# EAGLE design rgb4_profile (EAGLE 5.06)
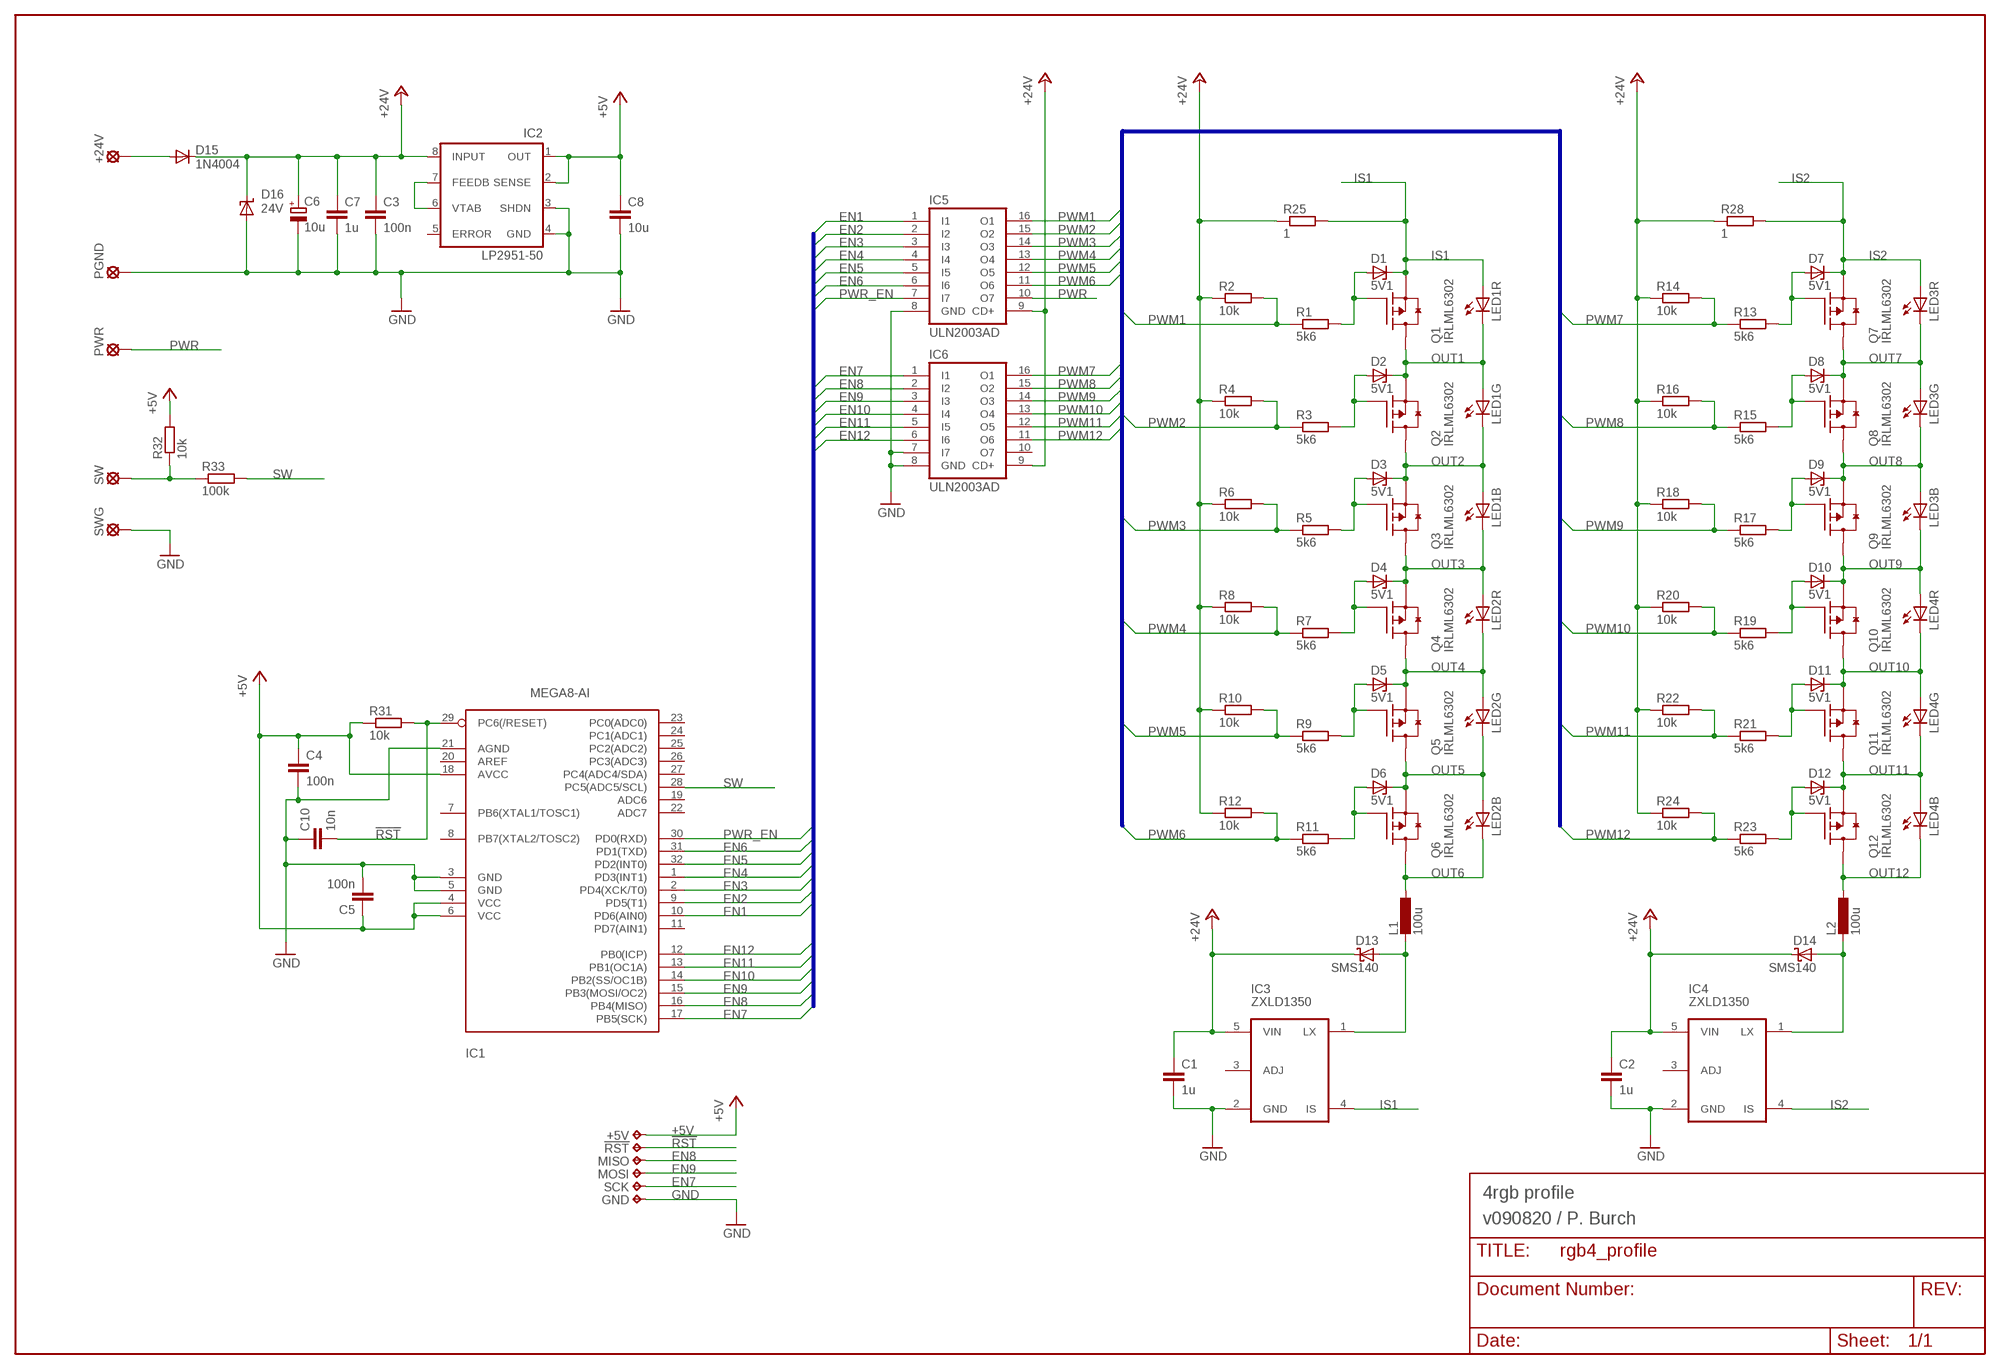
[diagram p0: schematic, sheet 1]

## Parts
!RST  TPB1,27  [B1,27]
+5V  TPB1,27  [B1,27]
+24V  SMD_4X2  [SMD4X2]
C1  1u  C-EUC1206  [C1206]
C2  1u  C-EUC1206  [C1206]
C3  100n  C-EUC0603  [C0603]
C4  100n  C-EUC0603  [C0603]
C5  100n  C-EUC0603  [C0603]
C6  10u  CPOL-EUD  [PANASONIC_D]
C7  1u  C-EUC1206  [C1206]
C8  10u  C-EUC1206  [C1206]
C10  10n  C-EUC0603  [C0603]
D1  5V1  ZENER-DIODESOD80C  [SOD80C]
D2  5V1  ZENER-DIODESOD80C  [SOD80C]
D3  5V1  ZENER-DIODESOD80C  [SOD80C]
D4  5V1  ZENER-DIODESOD80C  [SOD80C]
D5  5V1  ZENER-DIODESOD80C  [SOD80C]
D6  5V1  ZENER-DIODESOD80C  [SOD80C]
D7  5V1  ZENER-DIODESOD80C  [SOD80C]
D8  5V1  ZENER-DIODESOD80C  [SOD80C]
D9  5V1  ZENER-DIODESOD80C  [SOD80C]
D10  5V1  ZENER-DIODESOD80C  [SOD80C]
D11  5V1  ZENER-DIODESOD80C  [SOD80C]
D12  5V1  ZENER-DIODESOD80C  [SOD80C]
D13  SMS140  SCHOTTKY-DIODESMD  [SMB]
D14  SMS140  SCHOTTKY-DIODESMD  [SMB]
D15  1N4004  DIODE-MELF-MLL41  [MELF-MLL41]
D16  24V  SUPPRESSOR-SMBJ  [SMBJ]
GND  TPB1,27  [B1,27]
IC1  MEGA8-AI  [TQFP32-08]
IC2  LP2951-50  LP2951ACM  [SO-08]
IC3  ZXLD1350  [SOT23-5]
IC4  ZXLD1350  [SOT23-5]
IC5  ULN2003AD  [SO16]
IC6  ULN2003AD  [SO16]
L1  100u  L-EUX  [X]
L2  100u  L-EUX  [X]
LED1  SEOUL_ZPOWER_RGB  [SEOUL_P5]
LED2  SEOUL_ZPOWER_RGB  [SEOUL_P5]
LED3  SEOUL_ZPOWER_RGB  [SEOUL_P5]
LED4  SEOUL_ZPOWER_RGB  [SEOUL_P5]
MISO  TPB1,27  [B1,27]
MOSI  TPB1,27  [B1,27]
PGND  SMD_4X2  [SMD4X2]
PWR  SMD_4X2  [SMD4X2]
Q1  IRLML6302  [SOT23]
Q2  IRLML6302  [SOT23]
Q3  IRLML6302  [SOT23]
Q4  IRLML6302  [SOT23]
Q5  IRLML6302  [SOT23]
Q6  IRLML6302  [SOT23]
Q7  IRLML6302  [SOT23]
Q8  IRLML6302  [SOT23]
Q9  IRLML6302  [SOT23]
Q10  IRLML6302  [SOT23]
Q11  IRLML6302  [SOT23]
Q12  IRLML6302  [SOT23]
R1  5k6  R-EU_R0603  [R0603]
R2  10k  R-EU_R0603  [R0603]
R3  5k6  R-EU_R0603  [R0603]
R4  10k  R-EU_R0603  [R0603]
R5  5k6  R-EU_R0603  [R0603]
R6  10k  R-EU_R0603  [R0603]
R7  5k6  R-EU_R0603  [R0603]
R8  10k  R-EU_R0603  [R0603]
R9  5k6  R-EU_R0603  [R0603]
R10  10k  R-EU_R0603  [R0603]
R11  5k6  R-EU_R0603  [R0603]
R12  10k  R-EU_R0603  [R0603]
R13  5k6  R-EU_R0603  [R0603]
R14  10k  R-EU_R0603  [R0603]
R15  5k6  R-EU_R0603  [R0603]
R16  10k  R-EU_R0603  [R0603]
R17  5k6  R-EU_R0603  [R0603]
R18  10k  R-EU_R0603  [R0603]
R19  5k6  R-EU_R0603  [R0603]
R20  10k  R-EU_R0603  [R0603]
R21  5k6  R-EU_R0603  [R0603]
R22  10k  R-EU_R0603  [R0603]
R23  5k6  R-EU_R0603  [R0603]
R24  10k  R-EU_R0603  [R0603]
R25  1  R-EU_R0603  [R0603]
R28  1  R-EU_R0603  [R0603]
R31  10k  R-EU_R0603  [R0603]
R32  10k  R-EU_R0603  [R0603]
R33  100k  R-EU_R0603  [R0603]
SCK  TPB1,27  [B1,27]
SW  SMD_4X2  [SMD4X2]
SWG  SMD_4X2  [SMD4X2]

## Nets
!RST: !RST.PP(TP) C10.2 IC1.29(PC6(/RESET)) R31.2
+5V: +5V.PP(TP) C4.1 C5.1 C8.1 IC1.4(VCC) IC1.6(VCC) IC1.18(AVCC) IC2.1(OUT) IC2.2(SENSE) R31.1 R32.2
+24V: C1.1 C2.1 C3.1 C6.+ C7.1 D13.C D14.C D15.C D16.C IC2.8(INPUT) IC3.5(VIN) IC4.5(VIN) IC5.9(CD+) IC6.9(CD+) R2.1 R4.1 R6.1 R8.1 R10.1 R12.1 R14.1 R16.1 R18.1 R20.1 R22.1 R24.1 R25.1 R28.1
EN1: IC1.10(PD6(AIN0)) IC5.1(I1)
EN2: IC1.9(PD5(T1)) IC5.2(I2)
EN3: IC1.2(PD4(XCK/T0)) IC5.3(I3)
EN4: IC1.1(PD3(INT1)) IC5.4(I4)
EN5: IC1.32(PD2(INT0)) IC5.5(I5)
EN6: IC1.31(PD1(TXD)) IC5.6(I6)
EN7: IC1.17(PB5(SCK)) IC6.1(I1) SCK.PP(TP)
EN8: IC1.16(PB4(MISO)) IC6.2(I2) MISO.PP(TP)
EN9: IC1.15(PB3(MOSI/OC2)) IC6.3(I3) MOSI.PP(TP)
EN10: IC1.14(PB2(SS/OC1B)) IC6.4(I4)
EN11: IC1.13(PB1(OC1A)) IC6.5(I5)
EN12: IC1.12(PB0(ICP)) IC6.6(I6)
GND: C1.2 C2.2 C3.2 C4.2 C5.2 C6.- C7.2 C8.2 C10.1 D16.A GND.PP(TP) IC1.3(GND) IC1.5(GND) IC1.21(AGND) IC2.3(SHDN) IC2.4(GND) IC3.2(GND) IC4.2(GND) IC5.8(GND) IC6.7(I7) IC6.8(GND) PGND.PAD(MP) SWG.PAD(MP)
IS1: D1.C IC3.4(IS) LED1.RA(R:A) Q1.2(S) R25.2
IS2: D7.C IC4.4(IS) LED3.RA(R:A) Q7.2(S) R28.2
N$1: IC2.6(VTAB) IC2.7(FEEDB)
N$2: R32.1 R33.1 SW.PAD(MP)
N$3: D13.A IC3.1(LX) L1.P$2
N$4: D14.A IC4.1(LX) L2.P$2
N$5: D1.A Q1.1(G) R1.2
N$7: +24V.PAD(MP) D15.A
N$16: D2.A Q2.1(G) R3.2
N$17: D3.A Q3.1(G) R5.2
N$18: D4.A Q4.1(G) R7.2
N$19: D5.A Q5.1(G) R9.2
N$20: D6.A Q6.1(G) R11.2
N$21: D7.A Q7.1(G) R13.2
N$22: D8.A Q8.1(G) R15.2
N$23: D9.A Q9.1(G) R17.2
N$24: D10.A Q10.1(G) R19.2
N$25: D11.A Q11.1(G) R21.2
N$26: D12.A Q12.1(G) R23.2
OUT1: D2.C LED1.GA(G:A) LED1.RK(R:C) Q1.3(D) Q2.2(S)
OUT2: D3.C LED1.BA(B:A) LED1.GK(G:C) Q2.3(D) Q3.2(S)
OUT3: D4.C LED1.BK(B:C) LED2.RA(R:A) Q3.3(D) Q4.2(S)
OUT4: D5.C LED2.GA(G:A) LED2.RK(R:C) Q4.3(D) Q5.2(S)
OUT5: D6.C LED2.BA(B:A) LED2.GK(G:C) Q5.3(D) Q6.2(S)
OUT6: L1.P$1 LED2.BK(B:C) Q6.3(D)
OUT7: D8.C LED3.GA(G:A) LED3.RK(R:C) Q7.3(D) Q8.2(S)
OUT8: D9.C LED3.BA(B:A) LED3.GK(G:C) Q8.3(D) Q9.2(S)
OUT9: D10.C LED3.BK(B:C) LED4.RA(R:A) Q9.3(D) Q10.2(S)
OUT10: D11.C LED4.GA(G:A) LED4.RK(R:C) Q10.3(D) Q11.2(S)
OUT11: D12.C LED4.BA(B:A) LED4.GK(G:C) Q11.3(D) Q12.2(S)
OUT12: L2.P$1 LED4.BK(B:C) Q12.3(D)
PWM1: IC5.16(O1) R1.1 R2.2
PWM2: IC5.15(O2) R3.1 R4.2
PWM3: IC5.14(O3) R5.1 R6.2
PWM4: IC5.13(O4) R7.1 R8.2
PWM5: IC5.12(O5) R9.1 R10.2
PWM6: IC5.11(O6) R11.1 R12.2
PWM7: IC6.16(O1) R13.1 R14.2
PWM8: IC6.15(O2) R15.1 R16.2
PWM9: IC6.14(O3) R17.1 R18.2
PWM10: IC6.13(O4) R19.1 R20.2
PWM11: IC6.12(O5) R21.1 R22.2
PWM12: IC6.11(O6) R23.1 R24.2
PWR: IC5.10(O7) PWR.PAD(MP)
PWR_EN: IC1.30(PD0(RXD)) IC5.7(I7)
SW: IC1.28(PC5(ADC5/SCL)) R33.2
Unconnected: IC1.7(PB6(XTAL1/TOSC1)) IC1.8(PB7(XTAL2/TOSC2)) IC1.11(PD7(AIN1)) IC1.19(ADC6) IC1.20(AREF) IC1.22(ADC7) IC1.23(PC0(ADC0)) IC1.24(PC1(ADC1)) IC1.25(PC2(ADC2)) IC1.26(PC3(ADC3)) IC1.27(PC4(ADC4/SDA)) IC2.5(ERROR) IC3.3(ADJ) IC4.3(ADJ) IC6.10(O7)

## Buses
PWM:PWM[1..12]
SIG:EN[1..12],PWR_EN

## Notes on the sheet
- 4rgb profile
- v090820 / P. Burch

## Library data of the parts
!RST +5V GND MISO MOSI SCK = testpad:TP
+24V PGND PWR SW SWG = solpad:SMD: Single SMD pads
C1-C5 C7 C8 C10 = rcl:C-EU: CAPACITOR, European symbol
C6 = rcl:CPOL-EU: POLARIZED CAPACITOR, European symbol
D1-D12 = diode:ZENER-DIODE: Z-Diode
D13 D14 = diode:SCHOTTKY-DIODE: Schottky Diode
D15 = diode:DIODE-: DIODE
D16 = diode:SUPPRESSOR-: Suppressor diode
IC1 = avr-4:MEGA8: MICROCONTROLLER 8 Kbytes FLASH 1 kbytes SRAM 512 bytes EEPROM USART 6-channel 10 bit ADC 2-channel 8 bit ADC
IC2 = v-reg:LP2951?*: Series of Adjustable Micropower Voltage Regulators Source: http://cache.national.com/ds/LP/LP2950.pdf
IC3 IC4 = zetex:ZXLD1350: 350mA LED driver with internal switch Features: Supply voltage up to 30V High efficiency up to 95% Up to 1MHz switching frequency
IC5 IC6 = uln-udn:ULN2003A: DRIVER ARRAY
L1 L2 = rcl:L-EU: INDUCTOR, European symbol
LED1-LED4 = led:SEOUL_ZPOWER_RGB: Seould Z-Power RGB LED, 3 x 350mA
Q1-Q12 = transistor-fet:IRLML6302: P-Channel Enhancement MOSFET (HEXFET) RDSOn = 0.6R VDS = -20V IDS = 780mA
R1-R25 R28 R31-R33 = rcl:R-EU_: RESISTOR, European symbol

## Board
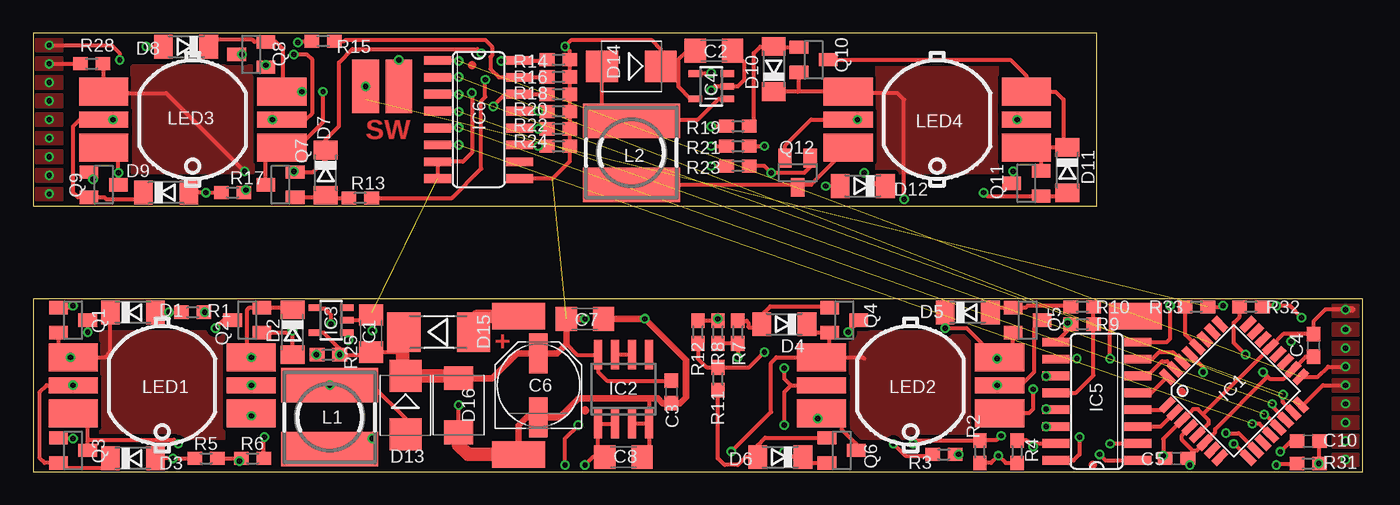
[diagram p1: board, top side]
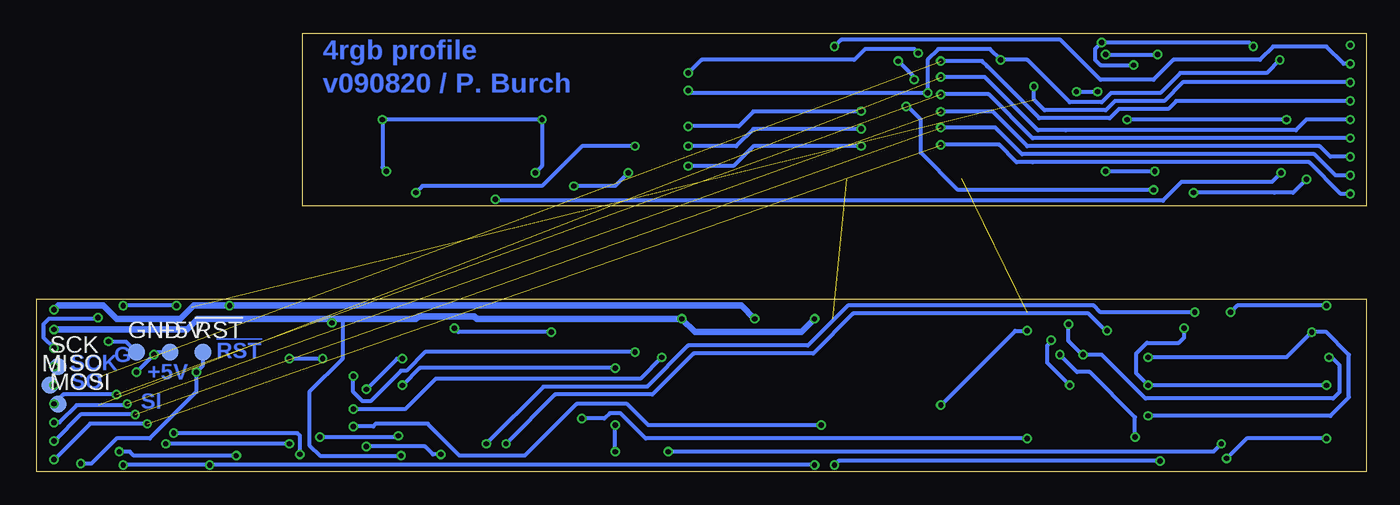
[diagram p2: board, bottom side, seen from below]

Size 100 x 33 mm. Coordinates in mm from the lower left corner, seen from the top.
Outline: 0,0 100,0 100,13 0,13 0,0
Outline: 0,20 80,20 80,33 0,33 0,20
Copper layers (1*16): Top 0.035mm / dielectric 1.5mm / Bottom 0.035mm
Design rules "PCB-POOL *": minimum track width 6mil, minimum drill 12mil, track to track 6mil, track to pad 6mil, pad to pad 6mil, via to via 6mil, smd to smd 0mil, copper to edge 0.1mm, drill to drill 8mil, minimum pad ring 8mil, minimum via ring 6mil, stop-mask expansion 3mil, vias tented up to drill 0mil, thermal gap 8mil

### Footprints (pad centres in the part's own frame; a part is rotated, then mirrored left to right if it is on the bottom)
B1,27 = smd 1.27 x 1.27: PP 0,0
SMD4X2 = smd 4 x 2: PAD 0,0
C1206 = smd 1.6 x 1.8: 1 -1.4,0; 2 1.4,0
C0603 = smd 1.1 x 1: 1 -0.85,0; 2 0.85,0
PANASONIC_D = smd 3 x 1.4: + 2.4,0; - -2.4,0
SOD80C = smd 1.4 x 1.8: A 1.7,0; C -1.7,0
SMB = smd 2.4 x 2.4: A 2.2,0; C -2.2,0
MELF-MLL41 = smd 2.5 x 3: A 2.625,0; C -2.625,0
SMBJ = smd 1.78 x 2.16: A 2.04,0; C -2.03,0
TQFP32-08 = smd 1.27 x 0.559: 1 -4.293,2.8; 2 -4.293,2; 3 -4.293,1.2; 4 -4.293,0.4; 5 -4.293,-0.4; 6 -4.293,-1.2; 7 -4.293,-2; 8 -4.293,-2.8; 17 4.293,-2.8; 18 4.293,-2; 19 4.293,-1.2; 20 4.293,-0.4; 21 4.293,0.4; 22 4.293,1.2; 23 4.293,2; 24 4.293,2.8 | smd 0.559 x 1.27: 9 -2.8,-4.293; 10 -2,-4.293; 11 -1.2,-4.293; 12 -0.4,-4.293; 13 0.4,-4.293; 14 1.2,-4.293; 15 2,-4.293; 16 2.8,-4.293; 25 2.8,4.293; 26 2,4.293; 27 1.2,4.293; 28 0.4,4.293; 29 -0.4,4.293; 30 -1.2,4.293; 31 -2,4.293; 32 -2.8,4.293
SO-08 = smd 0.6 x 2.2: 1 -1.905,-2.6; 2 -0.635,-2.6; 3 0.635,-2.6; 4 1.905,-2.6; 5 1.905,2.6; 6 0.635,2.6; 7 -0.635,2.6; 8 -1.905,2.6
SOT23-5 = smd 0.5 x 1: 1 -0.95,-1.2; 2 0,-1.2; 3 0.95,-1.2; 4 0.95,1.2; 5 -0.95,1.2
SO16 = smd 0.66 x 2.032: 1 -4.445,-3.073; 2 -3.175,-3.073; 3 -1.905,-3.073; 4 -0.635,-3.073; 5 0.635,-3.073; 6 1.905,-3.073; 7 3.175,-3.073; 8 4.445,-3.073; 9 4.445,3.073; 10 3.175,3.073; 11 1.905,3.073; 12 0.635,3.073; 13 -0.635,3.073; 14 -1.905,3.073; 15 -3.175,3.073; 16 -4.445,3.073
X = smd 7.3 x 2.6: P$1 0,2.4; P$2 0,-2.4
SEOUL_P5 = smd 3.7 x 1.2: BA 6.7,0; GK -6.7,0 | smd 3.7 x 2.1: BK 6.7,2.1; GA -6.7,-2.1; RA 6.7,-2.1; RK -6.7,2.1
SOT23 = smd 1 x 1.4: 1 -0.95,-1.1; 2 0.95,-1.1; 3 0,1.1
R0603 = smd 1.1 x 1: 1 -0.85,0; 2 0.85,0

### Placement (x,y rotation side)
!RST  87.5,9 0 bottom
+5V  90,9 0 bottom
+24V  36.5,11.7 0 top
C1  25.4,10.4 90 top
C2  51.2,31.7 0 top
C3  48,6 270 top
C4  96.3,9.5 90 top
C5  86,1 180 top
C6  38,6.5 90 top
C7  41.5,11.5 0 top
C8  44.4,1.1 0 top
C10  95.9,2.3 0 top
D1  7.5,12 0 top
D2  19.5,10.5 270 top
D3  7.5,1 0 top
D4  56.5,11.1 180 top
D5  70.3,12 0 top
D6  56.2,1.1 180 top
D7  22,22.5 270 top
D8  11.5,32 180 top
D9  10,21 0 top
D10  55.7,30.3 90 top
D11  77.8,22.7 270 top
D12  62.4,21.5 180 top
D13  28,5 270 top
D14  45,30.5 180 top
D15  30.5,10.5 0 top
D16  32,5 270 top
GND  92.5,9 0 bottom
IC1  90.32,6.08 45 top
IC2  44.4,6.2 0 top
IC3  22.4,11.4 90 top
IC4  51,29 90 top
IC5  80,5.3 90 top
IC6  33.5,26.5 270 top
L1  22.3,4.1 180 top
L2  45,24 180 top
LED1  9.7,6.5 180 top
LED2  66,6.5 180 top
LED3  12,26.5 180 top
LED4  68,26.5 180 top
MISO  99,6.5 0 bottom
MOSI  98.4,5.1 0 bottom
PGND  36.5,1.3 0 top
PWR  82.9,11.7 0 top
Q1  3,11.4 270 top
Q2  16.1,11.4 90 top
Q3  3,1.6 270 top
Q4  61,11.4 270 top
Q5  74.8,11.4 270 top
Q6  60.8,1.6 270 top
Q7  18.6,21.6 90 top
Q8  16.4,31.4 90 top
Q9  5.3,21.6 270 top
Q10  58.7,31 270 top
Q11  74.7,21.7 90 top
Q12  57.5,22.5 180 top
R1  12,12 180 top
R2  71.2,1.5 90 top
R3  68.5,1.3 180 top
R4  74,1.5 90 top
R5  13,1 180 top
R6  16.5,1 180 top
R7  53,10.5 90 top
R8  51.5,10.5 270 top
R9  78.9,12.4 180 top
R10  78.9,11.1 0 top
R11  51.5,7 270 top
R12  50,10.5 270 top
R13  24.6,20.6 180 top
R14  39.5,31 180 top
R15  21.8,32.4 180 top
R16  39.5,29.7 180 top
R17  15,21 180 top
R18  39.5,28.4 180 top
R19  53,26 0 top
R20  39.5,27.1 180 top
R21  53,24.5 0 top
R22  39.5,25.8 180 top
R23  53,23 0 top
R24  39.5,24.5 180 top
R25  22.2,8.8 180 top
R28  4.4,30.7 0 top
R31  95.9,0.6 0 top
R32  91.6,12.4 180 top
R33  87.5,12.4 180 top
SCK  98.4,7.9 0 bottom
SW  25,29 90 top
SWG  27.5,29 90 top

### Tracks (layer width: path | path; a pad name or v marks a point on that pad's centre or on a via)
!RST  (via drill 0.4)
  Top 0.3: C10.2 R31.2 v96.7,0.6 | IC1.29 88,7.83 v88,7.5
  Bottom 0.3: v96.7,0.6 95.9,0.6 94,2.5 91.5,2.5 88,6 v88,7.5 87.5,8 !RST.PP
+5V  (via drill 0.4)
  Top 0.3: IC2.2 IC2.1 42.49,1.6 C8.1 42.1,1.1 v41.5,0.5 | 92.9,7.1 v92.5,7.5 | 92.9,7.1 93,7 94.07,7 IC1.18 95.72,8.65 C4.1 | R32.2 90.75,11.65 90.3,11.2 90.3,9.7 v91.2,8.8 | 87,1 C5.1 | v87,0.5 87,1 | R31.1 93.6,0.6 v93.5,0.5 | IC1.4 86.4,2.73 86.4,2.4 87.2,1.6 | 87.2,1.6 87.54,1.6 IC1.6 88.9,2.96 88.9,3.2 92.8,7.1 92.9,7.1 | 87,1 87.2,1.2 87.2,1.6
  Bottom 0.3: v92.5,7.5 v91.2,8.8 91,9 +5V.PP | v41.5,0.5 v87,0.5 v93.5,0.5
+24V  (via drill 0.4)  (1 unrouted)
  Top 0.3: IC3.5 21.85,10.45 23.05,9.25 R25.1 25.2,8.8 C1.1 27.8,9 | C3.1 43.15,6.85 42.5,7.5 IC2.8 40.9,8.8 40.1,9.6 | R6.1 17.35,2.55 v17.4,2.6 | IC5.9 78.05,10.87 R10.1 77.9,11.1 v77.8,11.2 | R2.1 72.05,0.65 v72.6,1.2 73.15,0.65 R4.1 | R8.1 v51.5,11.5 51.35,11.35 R12.1 | v1.2,30.7 R28.1 | IC6.9 39.05,22.05 40.35,23.35 R24.1 R22.1 R20.1 R18.1 R16.1 R14.1 40.35,31.65 v40,32 40.5,32.5 46.5,32.5 47.2,31.8 47.2,31 | 47.2,31 D14.C | C2.1 49.2,31.7 48.5,31 | 47.2,31 48.5,31 | IC4.5 49.45,28.05 48.5,29 48.5,31
  Top 0.5: D16.C 34.53,7.03 36.4,8.9 C6.+ 39.4,8.9 40.1,9.6 C7.1 v41.5,11.5 | v98.7,10.7 98.9,10.7
  Top 1: D15.C 27.8,9 27.8,7.4 D13.C 31.83,7.2 D16.C
  Bottom 0.3: v17.4,2.6 17.4,4.1 20.8,7.5 21.75,7.5 R25.1 | v72.6,1.2 78.7,1.2 79.5,2 79.5,6 77,8.5 77,11.5 | v77.8,11.2 77.8,11.3 78,11.5 | v1.2,30.7 1.7,30.7 3,32 7,32 8,31 14.5,31 16,29.5 20,29.5 23,32.5 39.5,32.5 v40,32
  Bottom 0.5: v41.5,11.5 42.5,10.5 50.5,10.5 v51.5,11.5 66.9,11.5 67.1,11.7 71.3,11.7 71.5,11.5 77,11.5 78,11.5 87.9,11.5 88.7,10.7 v98.7,10.7
  other vias: 23.05,8.8
  pour Top: 99.7,10.2 99.7,11.2 97.7,11.2 97.7,10.2
  pour Top: 2.2,30.2 2.2,31.2 0.2,31.2 0.2,30.2
EN1  (via drill 0.4)
  Top 0.3: IC1.10 90.67,2.9 v89.7,2.9 | v80.2,1.3 80.64,0.85 IC5.1
  Bottom 0.3: v89.7,2.9 80.4,2.9 80.2,2.7 v80.2,1.3
EN2  (via drill 0.4)
  Top 0.3: IC5.2 81.03,2.12 v81,2.1 | v90.3,2.1 90.34,2.1 IC1.9
  Bottom 0.3: v81,2.1 v90.3,2.1
EN3
  Top 0.3: IC1.2 84.81,3.4 IC5.3
EN4
  Top 0.3: IC1.1 84.94,4.67 IC5.4
EN5
  Top 0.3: IC5.5 84.1,5.93 IC1.32
EN6
  Top 0.3: IC5.6 83.81,7.21 84.9,8.3 85.27,8.3 IC1.31
EN7  (via drill 0.4)  (1 unrouted)
  Top 0.3: IC1.17 96.64,7.13 97.4,7.9 v98.7,7.9 | 30.3,30.9 30.34,30.95 IC6.1 31.95,30.95 v32,30.9
  Bottom 0.3: v98.7,7.9 SCK.PP | v1.2,27.9 14.3,27.9 14.9,27.3 18.6,27.3 19.3,26.6 24.6,26.6 28.5,30.5 28.9,30.9 v32,30.9
  pour Top: 99.7,7.4 99.7,8.4 97.7,8.4 97.7,7.4
  pour Top: 2.2,27.4 2.2,28.4 0.2,28.4 0.2,27.4
EN8  (via drill 0.4)  (1 unrouted)
  Top 0.3: IC1.16 95.53,5.02 97,6.5 v98.7,6.5 | IC6.2 31.98,29.68 v32,29.7
  Bottom 0.3: v98.7,6.5 MISO.PP | v1.2,26.5 4.5,26.5 5.3,25.7 22.6,25.7 24.7,25.7 28.7,29.7 v32,29.7
  pour Top: 99.7,6 99.7,7 97.7,7 97.7,6
  pour Top: 2.2,26 2.2,27 0.2,27 0.2,26
EN9  (via drill 0.4)  (1 unrouted)
  Top 0.3: IC1.15 94,5.23 v94,5.8 | IC6.3 v32,28.41 v32,28.4
  Bottom 0.3: v94,5.8 98,5.8 v98.7,5.1 MOSI.PP | v32,28.4 28.4,28.4 25.1,25.1 v1.2,25.1
  pour Top: 99.7,4.6 99.7,5.6 97.7,5.6 97.7,4.6
  pour Top: 2.2,24.6 2.2,25.6 0.2,25.6 0.2,24.6
EN10  (via drill 0.4)  (1 unrouted)
  Top 0.3: IC1.14 93.2,4.9 v93.2,5.1 | IC6.4 31.96,27.14 v32,27.1
  Bottom 0.3: v93.2,5.1 93.3,5 97,5 98.3,3.7 v98.7,3.7 | v1.2,23.7 2.7,23.7 3.5,24.5 25.5,24.5 28.1,27.1 v32,27.1
  pour Top: 99.7,3.2 99.7,4.2 97.7,4.2 97.7,3.2
  pour Top: 2.2,23.2 2.2,24.2 0.2,24.2 0.2,23.2
EN11  (via drill 0.4)  (1 unrouted)
  Top 0.3: IC1.13 92.67,4.3 v92.6,4.3 | IC6.5 31.86,25.86 v32,25.9
  Bottom 0.3: v92.6,4.3 96.7,4.3 v98.7,2.3 | v1.2,22.3 2.3,22.3 3.9,23.9 25.9,23.9 27.9,25.9 v32,25.9
  pour Top: 99.7,1.8 99.7,2.8 97.7,2.8 97.7,1.8
  pour Top: 2.2,21.8 2.2,22.8 0.2,22.8 0.2,21.8
EN12  (via drill 0.4)  (1 unrouted)
  Top 0.3: IC1.12 92.23,3.6 v91.7,3.6 | IC6.6 v32,24.59 v32,24.6
  Bottom 0.3: v91.7,3.6 96,3.6 v98.7,0.9 | v1.2,20.9 1.9,20.9 4.3,23.3 25.1,23.3 26.3,23.3 27.6,24.6 v32,24.6
  pour Top: 99.7,0.4 99.7,1.4 97.7,1.4 97.7,0.4
  pour Top: 2.2,20.4 2.2,21.4 0.2,21.4 0.2,20.4
GND  (via drill 0.4)  (1 unrouted)
  Top 0.3: IC3.2 25,11.4 C1.2 25.4,11.9 25.5,12 v25.5,10.6 | D16.A v32,5 | IC2.4 46.3,5.5 | IC2.4 46.3,1.6 C8.2 | IC2.4 IC2.3 | 94.6,10.35 C4.2 96.3,11.3 97.2,12.2 v98.7,12.2 | 94.6,10.35 94.02,10.35 IC1.21 88.02,4.35 87.95,4.35 | IC5.8 85.25,9.74 85.5,10 v85.5,12.5 | C10.1 94.6,2.3 v93.8,1.5 | C5.2 85.05,1.15 v85,1.2 85,2.46 IC1.3 87.24,4.7 87.6,4.7 87.95,4.35 | 94.6,10.35 v94.6,9.8 | IC1.5 88.4,3.59 88.4,3.9 87.95,4.35 | v1.2,32.1 5.9,32.1 6.5,31.5 v6.5,31 | v27.5,31 SWG.PAD | IC6.8 IC6.7 32.33,23.32 33,24 v33,28.5 | C2.2 53.5,30.8 53.5,29.5 53,29 IC4.2 51.3,29 v51,28.7
  Top 0.5: PGND.PAD 36.5,3.5 37.1,4.1 C6.- 39.6,4.1 41,5.5 46.3,5.5 47,5.5 47.35,5.15 C3.2 48.65,5.15 49.1,5.6 49.1,8.4 v46,11.5 C7.2 | v98.7,12.2 99.2,12.2
  Top 1: PGND.PAD 32.7,1.3 32,2 D16.A
  Bottom 0.3: v93.8,1.5 93,1.5 92.7,1.2 v85,1.2 | v25.5,10.6 26.4,10.6 v32,5 | GND.PP 93.3,9.8 v94.6,9.8 | v6.5,31 7.5,30 14,30 15.5,28.5 19.2,28.5 19.9,27.8 22.3,27.8 25.5,31 v27.5,31 28.3,31.8 32.2,31.8 33,31 v33,28.5 50.8,28.5 v51,28.7
  Bottom 0.5: v46,11.5 47,12.5 v85.5,12.5 88.2,12.5 89.2,11.5 94,11.5 95,12.5 98.4,12.5 v98.7,12.2
  pour Top: 99.7,11.6 99.7,12.6 97.7,12.6 97.7,11.6
  pour Top: 2.2,31.6 2.2,32.6 0.2,32.6 0.2,31.6
IS1  (via drill 0.4)
  Top 0.3: LED1.RA 3,8.5 2,8.5 1.9,8.6 Q1.2 | v2.8,8.6 LED1.RA | IC3.4 21.3,12.25 21.95,12.25 22.4,11.8 v22.4,11.1 | v21.3,8.8 R25.2 | D1.C 5.8,9 5.4,8.6 LED1.RA
  Bottom 0.3: v2.8,8.6 2.6,8.6 2,8 2,6 2.5,5.5 16.6,5.5 19.9,8.8 v21.3,8.8 R25.2 22.4,9.85 v22.4,11.1
  pour Top (isolate 0.3): 5.1,10.5 14.3,10.5 14.3,2.5 5.1,2.5
IS2  (via drill 0.4)
  Top 0.3: R28.2 5.3,30.65 LED3.RA 5.4,28.5 10,28.5 v15.9,22.6 | v19.6,22.6 19.65,22.55 Q7.2 21.05,22.55 22,23.5 D7.C 22,25 23,26 23,30.8 24,31.8 33.4,31.8 v33.7,31.5 | IC4.4 50.95,29.95 v51,30
  Bottom 0.3: v15.9,22.6 v19.6,22.6 | v33.7,31.5 34,31.8 37.7,31.8 38.5,31 50,31 v51,30
  pour Top (isolate 0.3): 8,30.5 16.5,30.5 16.5,22.5 7.5,22.5 7.5,30.5
N$1
  Top 0.3: IC2.6 IC2.7
N$2  (via drill 0.4)  (1 unrouted)
  Top 0.3: v98.7,9.3 98.9,9.3 | R33.1 89.4,12.4 v89.5,12.5 | R32.1 92.55,12.5 v93.5,12.5 94.5,12.5 v95.4,11.6
  Bottom 0.3: v98.7,9.3 99.5,10.1 99.5,11.1 99.1,11.5 95.5,11.5 v95.4,11.6 | v89.5,12.5 v93.5,12.5 | v1.2,29.3 13.8,29.3 15.2,27.9 18.9,27.9 19.6,27.2 24.2,27.2 25,28 SW.PAD
  other vias: 25,29
  pour Top: 99.7,8.8 99.7,9.8 97.7,9.8 97.7,8.8
  pour Top: 2.2,28.8 2.2,29.8 0.2,29.8 0.2,28.8
N$3  (via drill 0.4)
  Top 0.3: 23,6.5 L1.P$2 25.5,6.5 28,4 D13.A | v23.7,9.9 23.7,10.35 IC3.1
  Bottom 0.3: v23.7,9.9 23.7,9.8 24,9.5 24,8.2 L1.P$2
  other vias: 22.3,6.5
N$4
  Top 0.3: IC4.1 51.55,28.05 50,26.5 45.1,26.5 L2.P$2 44.9,26.5 43,26.5 42.8,26.7 D14.A
N$5  (via drill 0.4)
  Top 0.3: Q1.1 2.85,12.35 v3,12.5 | D1.A v10.2,12 R1.2
  Bottom 0.3: v3,12.5 9.7,12.5 v10.2,12
N$7
  Top 1: +24V.PAD 33.4,11.7 D15.A
N$16  (via drill 0.4)
  Top 0.3: R3.2 67.6,1.3 67.5,1.2 65.6,1.2 v64.7,2.1 | Q2.1 19.35,10.45 v19.5,10.6 D2.A
  Bottom 0.3: v64.7,2.1 61,5.8 53.7,5.8 50.6,8.9 41.6,8.9 38.6,11.9 20.9,11.9 19.6,10.6 v19.5,10.6
N$17  (via drill 0.4)
  Top 0.3: Q3.1 2.95,2.55 v3,2.5 | D3.A v10.5,1 R5.2
  Bottom 0.3: v3,2.5 9,2.5 v10.5,1
N$18
  Top 0.3: R7.2 53.65,11.35 53.8,11.2 53.8,10.9 53.85,10.85 54.75,10.85 54.75,11.05 D4.A 55,11.3 55,12 55.45,12.45 59.8,12.45 Q4.1
N$19
  Top 0.3: D5.A 72.35,12.35 Q5.1 74.65,12.35 74.8,12.5 77.95,12.5 R9.2
N$20
  Top 0.3: R11.2 51.5,1 52,0.5 53,0.5 53.6,1.1 D6.A 54.5,2 55.05,2.55 Q6.1
N$21
  Top 0.3: Q7.1 21.85,20.65 D7.A 22.2,20.6 R13.2
N$22  (via drill 0.4)
  Top 0.3: D8.A v8.5,32 | v17.5,30.6 Q8.1 | R15.2 20,32.4 v19.9,32.3
  Bottom 0.3: v8.5,32 8.8,32.3 v19.9,32.3 20.4,31.8 20.4,31 20,30.6 v17.5,30.6
N$23  (via drill 0.4)
  Top 0.3: D9.A v13,21 R17.2 | Q9.1 4.2,22.3 v4.5,22
  Bottom 0.3: v13,21 6.9,21 5.5,21 v4.5,22
N$24
  Top 0.3: Q10.1 55.15,31.95 D10.A 54.7,32 54.2,31.5 54.2,26.35 R19.2
N$25  (via drill 0.4)
  Top 0.3: D11.A 77.55,20.75 Q11.1 71.75,20.75 v71.5,21 | R21.2 v55,24.5
  Bottom 0.3: v55,24.5 59,24.5 62,21.5 71,21.5 v71.5,21
N$26  (via drill 0.4)
  Top 0.3: Q12.1 58.45,22.95 58,22.5 v55.5,22.5 55,23 R23.2 | v59.6,21.5 D12.A
  Bottom 0.3: v59.6,21.5 56.5,21.5 v55.5,22.5
OUT1  (via drill 0.4)
  Top 0.3: 16.2,8.8 LED1.GA 16.1,8.9 16.1,12.2 16.25,12.35 Q2.2 19.35,12.35 D2.C | v16.4,4.2 LED1.RK | v4.1,10.5 Q1.3
  Bottom 0.3: v16.4,4.2 2.7,4.2 1.3,5.6 1.3,8.8 3,10.5 v4.1,10.5 6,8.6 LED1.GA
  other vias: 16.4,8.6
OUT2  (via drill 0.4)
  Top 0.3: LED1.GK 15.7,6.5 | 3.5,6.5 LED1.BA 1,6.5 0.5,6 0.5,1 0.85,0.65 Q3.2 2.15,0.55 2.4,0.3 5.6,0.3 5.7,0.4 5.7,0.9 D3.C | Q2.3 14.4,11.5 v13.7,10.8
  Bottom 0.3: LED1.BA LED1.GK 17.3,7.4 17.3,8.9 16.5,9.7 14.1,9.7 13.7,10.1 v13.7,10.8
  other vias: 16.4,6.5 3,6.5
OUT3  (via drill 0.4)
  Top 0.3: LED1.BK 3.4,4 4,4 4.1,3.9 4.1,2.5 | v10.9,2.1 10.6,2.4 4.2,2.4 4.1,2.5 | LED2.RA 60,8.6 59.9,8.7 Q4.2 58.85,10.45 D4.C | v52.5,1.5 55.5,4.5 55.5,8.2 55.9,8.6 LED2.RA | Q3.3 4.1,2.5 | LED2.RA 62.4,8.6 62.5,8.5
  Bottom 0.3: v52.5,1.5 11.5,1.5 v10.9,2.1
  pour Top (isolate 0.3): 61.5,10.5 70.5,10.5 70.5,2.5 61.5,2.5
OUT4  (via drill 0.4)
  Top 0.3: 72.6,4.4 LED2.RK 74.9,4.4 75.2,4.7 v75.2,6.2 | Q4.3 62.1,11.3 v61.3,10.5 | D5.C v68.6,10.8 70.2,10.8 v72.5,8.5 72.6,8.6 LED2.GA 73.7,9.6 Q5.2
  Bottom 0.3: v72.5,8.5 72.9,8.5 v75.2,6.2 | v61.3,10.5 68.3,10.5 v68.6,10.8
OUT5  (via drill 0.4)
  Top 0.3: v56.5,3.5 56.5,6 57,6.5 | 57,6.5 LED2.BA 60,6.5 | 57,6.5 56.5,7 v56.5,7.8 | v72.5,6.5 LED2.GK 74.3,6.5 75.3,7.5 75.3,10.8 Q5.3 | Q6.2 58.35,0.65 D6.C 56.9,1.1 v56.5,1.5
  Bottom 0.3: v72.5,6.5 71.2,7.8 v56.5,7.8 | v56.5,1.5 v56.5,3.5
OUT6  (via drill 0.4)
  Top 0.3: LED2.BK 60.1,4.4 60.8,3.7 60.8,3.2 61.9,2.1 Q6.3 | L1.P$1 24.7,1.7 v25.5,2.5 | LED2.BK 58.7,4.4 | v59,4 59,4.1 LED2.BK
  Bottom 0.3: v25.5,2.5 54.2,2.5 56.1,4.4 56.9,4.4 57.3,4 v59,4
OUT7  (via drill 0.4)
  Top 0.3: LED3.RK 18.8,24.4 | D8.C 13.7,32.5 16.5,32.5 16.65,32.35 Q8.2 18.25,32.35 18.8,31.8 18.8,28.6 LED3.GA v20.2,28.6 | v21.8,28.6 21.8,26.3 20,24.5 18.8,24.5 LED3.RK | Q7.3 17.5,24 18.3,24 LED3.RK
  Bottom 0.3: v21.8,28.6 v20.2,28.6
OUT8  (via drill 0.4)
  Top 0.3: v18,26.5 LED3.GK 20.5,26.5 21,27 21,31 20.6,31.4 v19.6,31.4 | LED3.BA v6,26.5 3.5,26.5 3,26 3,21 3.35,20.65 Q9.2 5.35,20.65 5.5,20.5 7.8,20.5 D9.C | v15.7,31.4 Q8.3
  Bottom 0.3: v6,26.5 v18,26.5 | v19.6,31.4 v15.7,31.4
OUT9  (via drill 0.4)
  Top 0.3: Q9.3 v6.4,22.5 6.4,23.9 6.5,24 5.7,24 LED3.BK | v65.5,20.5 65.5,28 65,28.5 61.4,28.5 LED4.RA 57.5,28.6 | 57.5,28.6 D10.C | Q10.2 57.6,28.7 57.5,28.6
  Bottom 0.3: v6.4,22.5 7.1,21.8 13.9,21.8 15.3,20.4 65.4,20.4 v65.5,20.5
  pour Top (isolate 0.3): 63.5,30.5 72.5,30.5 72.5,22.5 63.5,22.5
OUT10
  Top 0.3: 76,24.4 LED4.RK | 76,24.4 D11.C 77.5,24.7 77.5,28 76.9,28.6 LED4.GA 74.7,29.8 73.5,31 Q10.3 | Q11.2 75.8,24.2 76,24.4
OUT11  (via drill 0.4)
  Top 0.3: v74,26.5 LED4.GK | v62,26.5 LED4.BA 58.5,26.5 56.55,24.55 Q12.2 | Q11.3 73.6,22.5 v73.7,22.6 | v62.5,22.5 63.5,21.5 D12.C
  Bottom 0.3: v73.7,22.6 74,22.9 v74,26.5 v62,26.5 62,23 v62.5,22.5
OUT12
  Top 0.3: L2.P$1 58.5,21.6 | 58.5,21.6 LED4.BK | 58.5,21.6 57.7,21.6 Q12.3
PWM1  (via drill 0.4)
  Top 0.3: IC5.16 78.25,0.85 78.7,1.3 v78.7,2.6 | v72.8,2.7 72.5,2.4 71.25,2.4 R2.2 66.45,2.35 v66.2,2.1 | R1.1 v12.9,12
  Bottom 0.3: v78.7,2.6 72.9,2.6 v72.8,2.7 | v12.9,12 20,12 20.5,12.5 39,12.5 42,9.5 51,9.5 54.1,6.4 61.9,6.4 v66.2,2.1
PWM2  (via drill 0.4)
  Top 0.3: IC5.15 75.42,2.12 v75.2,1.9 74.75,2.35 R4.2 | R3.1 v69.6,1.3
  Bottom 0.3: v75.2,1.9 70.8,1.9 70.2,1.3 v69.6,1.3
PWM3  (via drill 0.4)
  Top 0.3: R5.1 R6.2 15.65,0.95 v15.5,0.8 | IC5.14 v76.2,3.4 | v40,0.5 40,2.5 v41,3.5
  Bottom 0.3: v76.2,3.4 74.7,3.4 74.5,3.6 70.6,3.6 68.2,1.2 63.3,1.2 59.4,5.1 55.6,5.1 54,3.5 v41,3.5 | v15.5,0.8 39.7,0.8 v40,0.5
PWM4  (via drill 0.4)
  Top 0.3: 76.86,4.67 IC5.13 76.89,4.7 v76.2,4.7 | R8.2 R7.1 v53,8.6
  Bottom 0.3: v53,8.6 54.6,7 70,7 72.3,4.7 v76.2,4.7
PWM5
  Top 0.3: R9.1 R10.2 79.75,7.25 78.44,5.93 IC5.12
PWM6  (via drill 0.4)
  Top 0.3: v76.2,7.2 IC5.11 | R12.2 50,8.5 50.65,7.85 R11.1 53.85,7.85 v55,9
  Bottom 0.3: v76.2,7.2 76.2,6 75.5,5.3 74.9,5.3 72.6,7.6 72.2,7.6 70.8,9 v55,9
PWM7  (via drill 0.4)
  Top 0.3: R14.2 38.65,30.95 IC6.16 35.24,30.95 v35.2,30.9 | R13.1 31.5,20.6 33.7,22.8 33.7,27.9 34,28.2 v34,29.5
  Bottom 0.3: v35.2,30.9 34,29.7 v34,29.5
PWM8
  Top 0.3: R16.2 38.65,29.68 IC6.15 35.02,29.68 34.4,30.3 34.4,31.2 34.5,31.3 34.5,32 34,32.5 23.5,32.5 23.4,32.4 R15.1
PWM9  (via drill 0.4)
  Top 0.3: R18.2 IC6.14 35.51,28.41 v34.6,27.5 | R17.1 v16,21.2
  Bottom 0.3: v34.6,27.5 34.5,27.5 33.5,26.5 33.5,24 30.7,21.2 v16,21.2
PWM10  (via drill 0.4)
  Top 0.3: IC6.13 37.5,27.14 v38,27.14 38.65,27.14 R20.2 | v51,26 R19.1
  Bottom 0.3: v51,26 47.2,26 46.1,27.1 38.03,27.1 v38,27.14
PWM11  (via drill 0.4)
  Top 0.3: IC6.12 38.65,25.86 R22.2 v38,25.8 | v51,24.5 R21.1
  Bottom 0.3: v51,24.5 47.4,24.5 46.1,25.8 v38,25.8
PWM12  (via drill 0.4)
  Top 0.3: IC6.11 38.65,24.59 R24.2 v38,24.5 | v51,23 R23.1
  Bottom 0.3: v51,23 47.6,23 46.1,24.5 v38,24.5
PWR  (via drill 0.4)
  Top 0.3: IC5.10 78.47,8.47 v78.5,8.5 | v81,8.5 81,10.5 82,11.5 82.7,11.5 PWR.PAD
  Bottom 0.3: v78.5,8.5 v81,8.5
PWR_EN
  Top 0.3: IC5.7 84.17,8.47 84.7,9 85.7,9 IC1.30
SW
  Top 0.3: IC1.28 86.65,10.32 R33.2
(copper drawn outside any net)
  shapes: Top circle x4

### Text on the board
Top: SW | +
Bottom: 4rgb profile | v090820 / P. Burch | !RST | G | SCK | +5V | SO | SI
tStop: -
